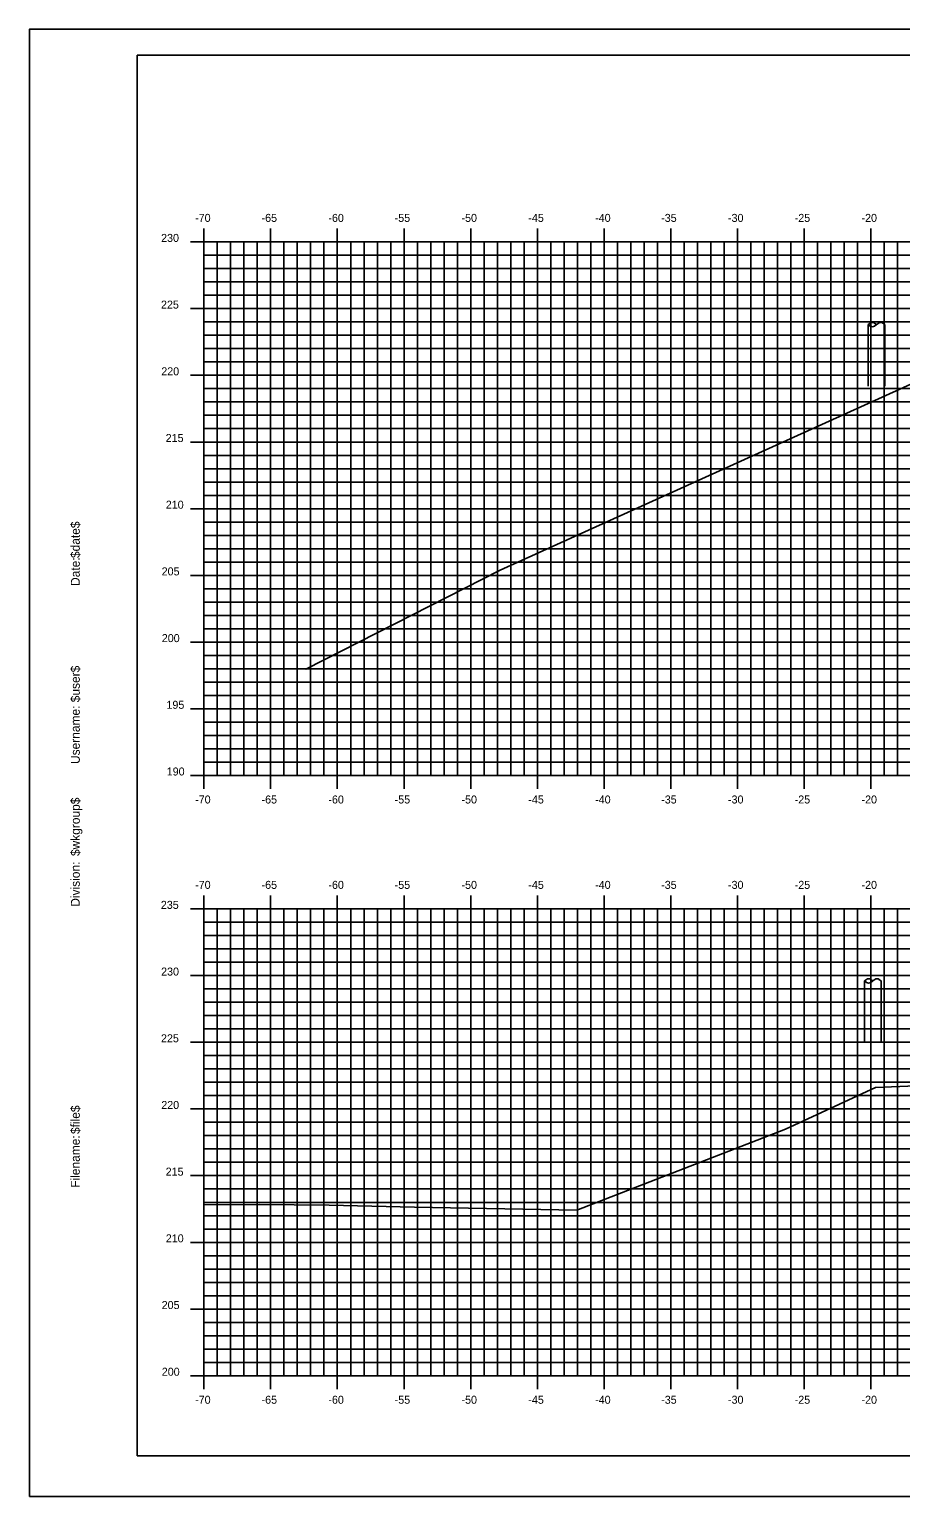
# Model space of a CAD drawing. Extents: x 1138098 to 1138268, y 608981 to 609091.
# Drawn here: x 1138097.8 to 1138163.2, y 608981.3 to 609091.3 of the extents above; entities that cross this region are included whole.
import ezdxf

# ---------------------------------------------------------------- set-up
doc = ezdxf.new("R2010")
doc.units = 0
for name, color, linetype in [('BORDER', 7, 'Continuous'), ('H_V ANNOTATION', 7, 'Continuous'), ('MAJOR', 7, 'Continuous'), ('MINOR', 7, 'Continuous'), ('PLOT BOUNDARY', 7, 'Continuous'), ('S_Roadway_Centerline', 7, 'Continuous'), ('S_Utilities_Pole_Power', 7, 'Continuous')]:
    doc.layers.add(name, color=color, linetype=linetype)

msp = doc.modelspace()

# ---------------------------------------------------------------- linework, layer by layer
at = {"layer": 'BORDER'}
msp.add_lwpolyline([(1138105.92, 608984.34), (1138265.92, 608984.34), (1138265.92, 609089.34), (1138105.92, 609089.34)], close=True, dxfattribs=at)
at = {"layer": 'MAJOR'}
for p, q in [((1138110.92, 609076.34), (1138110.92, 609075.34)), ((1138115.92, 609076.34), (1138115.92, 609075.34)), ((1138120.92, 609076.34), (1138120.92, 609075.34)), ((1138125.92, 609076.34), (1138125.92, 609075.34)), ((1138130.92, 609076.34), (1138130.92, 609075.34)), ((1138135.92, 609076.34), (1138135.92, 609075.34)), ((1138140.92, 609076.34), (1138140.92, 609075.34)), ((1138145.92, 609076.34), (1138145.92, 609075.34)), ((1138150.92, 609076.34), (1138150.92, 609075.34)), ((1138155.92, 609076.34), (1138155.92, 609075.34)), ((1138160.92, 609076.34), (1138160.92, 609075.34)), ((1138109.92, 609075.34), (1138110.92, 609075.34)), ((1138110.92, 609075.34), (1138250.92, 609075.34)), ((1138110.92, 609035.34), (1138110.92, 609075.34)), ((1138110.92, 609035.34), (1138110.92, 609075.34)), ((1138110.92, 609075.34), (1138250.92, 609075.34)), ((1138115.92, 609035.34), (1138115.92, 609075.34)), ((1138120.92, 609035.34), (1138120.92, 609075.34)), ((1138125.92, 609035.34), (1138125.92, 609075.34)), ((1138130.92, 609035.34), (1138130.92, 609075.34)), ((1138135.92, 609035.34), (1138135.92, 609075.34)), ((1138140.92, 609035.34), (1138140.92, 609075.34)), ((1138145.92, 609035.34), (1138145.92, 609075.34)), ((1138150.92, 609035.34), (1138150.92, 609075.34)), ((1138155.92, 609035.34), (1138155.92, 609075.34)), ((1138160.92, 609035.34), (1138160.92, 609075.34)), ((1138109.92, 609070.34), (1138110.92, 609070.34)), ((1138110.92, 609070.34), (1138250.92, 609070.34)), ((1138109.92, 609065.34), (1138110.92, 609065.34)), ((1138110.92, 609065.34), (1138250.92, 609065.34)), ((1138109.92, 609060.34), (1138110.92, 609060.34)), ((1138110.92, 609060.34), (1138250.92, 609060.34)), ((1138109.92, 609055.34), (1138110.92, 609055.34)), ((1138110.92, 609055.34), (1138250.92, 609055.34)), ((1138109.92, 609050.34), (1138110.92, 609050.34)), ((1138110.92, 609050.34), (1138250.92, 609050.34)), ((1138109.92, 609045.34), (1138110.92, 609045.34)), ((1138110.92, 609045.34), (1138250.92, 609045.34)), ((1138109.92, 609040.34), (1138110.92, 609040.34)), ((1138110.92, 609040.34), (1138250.92, 609040.34)), ((1138109.92, 609035.34), (1138110.92, 609035.34)), ((1138110.92, 609035.34), (1138250.92, 609035.34)), ((1138110.92, 609035.34), (1138250.92, 609035.34)), ((1138110.92, 609034.33), (1138110.92, 609035.34)), ((1138115.92, 609034.33), (1138115.92, 609035.34)), ((1138120.92, 609034.33), (1138120.92, 609035.34)), ((1138125.92, 609034.33), (1138125.92, 609035.34)), ((1138130.92, 609034.33), (1138130.92, 609035.34)), ((1138135.92, 609034.33), (1138135.92, 609035.34)), ((1138140.92, 609034.33), (1138140.92, 609035.34)), ((1138145.92, 609034.33), (1138145.92, 609035.34)), ((1138150.92, 609034.33), (1138150.92, 609035.34)), ((1138155.92, 609034.33), (1138155.92, 609035.34)), ((1138160.92, 609034.33), (1138160.92, 609035.34)), ((1138110.92, 609026.34), (1138110.92, 609025.34)), ((1138115.92, 609026.34), (1138115.92, 609025.34)), ((1138120.92, 609026.34), (1138120.92, 609025.34)), ((1138125.92, 609026.34), (1138125.92, 609025.34)), ((1138130.92, 609026.34), (1138130.92, 609025.34)), ((1138135.92, 609026.34), (1138135.92, 609025.34)), ((1138140.92, 609026.34), (1138140.92, 609025.34)), ((1138145.92, 609026.34), (1138145.92, 609025.34)), ((1138150.92, 609026.34), (1138150.92, 609025.34)), ((1138155.92, 609026.34), (1138155.92, 609025.34)), ((1138160.92, 609026.34), (1138160.92, 609025.34)), ((1138109.92, 609025.34), (1138110.92, 609025.34)), ((1138110.92, 609025.34), (1138250.92, 609025.34)), ((1138110.92, 608990.34), (1138110.92, 609025.34)), ((1138110.92, 608990.34), (1138110.92, 609025.34)), ((1138110.92, 609025.34), (1138250.92, 609025.34)), ((1138115.92, 608990.34), (1138115.92, 609025.34)), ((1138120.92, 608990.34), (1138120.92, 609025.34)), ((1138125.92, 608990.34), (1138125.92, 609025.34)), ((1138130.92, 608990.34), (1138130.92, 609025.34)), ((1138135.92, 608990.34), (1138135.92, 609025.34)), ((1138140.92, 608990.34), (1138140.92, 609025.34)), ((1138145.92, 608990.34), (1138145.92, 609025.34)), ((1138150.92, 608990.34), (1138150.92, 609025.34)), ((1138155.92, 608990.34), (1138155.92, 609025.34)), ((1138160.92, 608990.34), (1138160.92, 609025.34)), ((1138109.92, 609020.34), (1138110.92, 609020.34)), ((1138110.92, 609020.34), (1138250.92, 609020.34)), ((1138109.92, 609015.34), (1138110.92, 609015.34)), ((1138110.92, 609015.34), (1138250.92, 609015.34)), ((1138109.92, 609010.34), (1138110.92, 609010.34)), ((1138110.92, 609010.34), (1138250.92, 609010.34)), ((1138109.92, 609005.34), (1138110.92, 609005.34)), ((1138110.92, 609005.34), (1138250.92, 609005.34)), ((1138109.92, 609000.34), (1138110.92, 609000.34)), ((1138110.92, 609000.34), (1138250.92, 609000.34)), ((1138109.92, 608995.34), (1138110.92, 608995.34)), ((1138110.92, 608995.34), (1138250.92, 608995.34)), ((1138109.92, 608990.34), (1138110.92, 608990.34)), ((1138110.92, 608990.34), (1138250.92, 608990.34)), ((1138110.92, 608990.34), (1138250.92, 608990.34)), ((1138110.92, 608989.33), (1138110.92, 608990.34)), ((1138115.92, 608989.33), (1138115.92, 608990.34)), ((1138120.92, 608989.33), (1138120.92, 608990.34)), ((1138125.92, 608989.33), (1138125.92, 608990.34)), ((1138130.92, 608989.33), (1138130.92, 608990.34)), ((1138135.92, 608989.33), (1138135.92, 608990.34)), ((1138140.92, 608989.33), (1138140.92, 608990.34)), ((1138145.92, 608989.33), (1138145.92, 608990.34)), ((1138150.92, 608989.33), (1138150.92, 608990.34)), ((1138155.92, 608989.33), (1138155.92, 608990.34)), ((1138160.92, 608989.33), (1138160.92, 608990.34))]:
    msp.add_line(p, q, dxfattribs=at)
at = {"layer": 'MINOR'}
for p, q in [((1138111.92, 609035.34), (1138111.92, 609075.34)), ((1138112.92, 609035.34), (1138112.92, 609075.34)), ((1138113.92, 609035.34), (1138113.92, 609075.34)), ((1138114.92, 609035.34), (1138114.92, 609075.34)), ((1138116.92, 609035.34), (1138116.92, 609075.34)), ((1138117.92, 609035.34), (1138117.92, 609075.34)), ((1138118.92, 609035.34), (1138118.92, 609075.34)), ((1138119.92, 609035.34), (1138119.92, 609075.34)), ((1138121.92, 609035.34), (1138121.92, 609075.34)), ((1138122.92, 609035.34), (1138122.92, 609075.34)), ((1138123.92, 609035.34), (1138123.92, 609075.34)), ((1138124.92, 609035.34), (1138124.92, 609075.34)), ((1138126.92, 609035.34), (1138126.92, 609075.34)), ((1138127.92, 609035.34), (1138127.92, 609075.34)), ((1138128.92, 609035.34), (1138128.92, 609075.34)), ((1138129.92, 609035.34), (1138129.92, 609075.34)), ((1138131.92, 609035.34), (1138131.92, 609075.34)), ((1138132.92, 609035.34), (1138132.92, 609075.34)), ((1138133.92, 609035.34), (1138133.92, 609075.34)), ((1138134.92, 609035.34), (1138134.92, 609075.34)), ((1138136.92, 609035.34), (1138136.92, 609075.34)), ((1138137.92, 609035.34), (1138137.92, 609075.34)), ((1138138.92, 609035.34), (1138138.92, 609075.34)), ((1138139.92, 609035.34), (1138139.92, 609075.34)), ((1138141.92, 609035.34), (1138141.92, 609075.34)), ((1138142.92, 609035.34), (1138142.92, 609075.34)), ((1138143.92, 609035.34), (1138143.92, 609075.34)), ((1138144.92, 609035.34), (1138144.92, 609075.34)), ((1138146.92, 609035.34), (1138146.92, 609075.34)), ((1138147.92, 609035.34), (1138147.92, 609075.34)), ((1138148.92, 609035.34), (1138148.92, 609075.34)), ((1138149.92, 609035.34), (1138149.92, 609075.34)), ((1138151.92, 609035.34), (1138151.92, 609075.34)), ((1138152.92, 609035.34), (1138152.92, 609075.34)), ((1138153.92, 609035.34), (1138153.92, 609075.34)), ((1138154.92, 609035.34), (1138154.92, 609075.34)), ((1138156.92, 609035.34), (1138156.92, 609075.34)), ((1138157.92, 609035.34), (1138157.92, 609075.34)), ((1138158.92, 609035.34), (1138158.92, 609075.34)), ((1138159.92, 609035.34), (1138159.92, 609075.34)), ((1138161.92, 609035.34), (1138161.92, 609075.34)), ((1138162.92, 609035.34), (1138162.92, 609075.34)), ((1138110.92, 609074.34), (1138250.92, 609074.34)), ((1138110.92, 609074.34), (1138111.92, 609074.34)), ((1138110.92, 609073.34), (1138250.92, 609073.34)), ((1138110.92, 609073.34), (1138111.92, 609073.34)), ((1138110.92, 609072.34), (1138250.92, 609072.34)), ((1138110.92, 609072.34), (1138111.92, 609072.34)), ((1138110.92, 609071.34), (1138250.92, 609071.34)), ((1138110.92, 609071.34), (1138111.92, 609071.34)), ((1138110.92, 609069.34), (1138250.92, 609069.34)), ((1138110.92, 609069.34), (1138111.92, 609069.34)), ((1138110.92, 609068.34), (1138250.92, 609068.34)), ((1138110.92, 609068.34), (1138111.92, 609068.34)), ((1138110.92, 609067.34), (1138250.92, 609067.34)), ((1138110.92, 609067.34), (1138111.92, 609067.34)), ((1138110.92, 609066.34), (1138250.92, 609066.34)), ((1138110.92, 609066.34), (1138111.92, 609066.34)), ((1138110.92, 609064.34), (1138250.92, 609064.34)), ((1138110.92, 609064.34), (1138111.92, 609064.34)), ((1138110.92, 609063.34), (1138250.92, 609063.34)), ((1138110.92, 609063.34), (1138111.92, 609063.34)), ((1138110.92, 609062.34), (1138250.92, 609062.34)), ((1138110.92, 609062.34), (1138111.92, 609062.34)), ((1138110.92, 609061.34), (1138250.92, 609061.34)), ((1138110.92, 609061.34), (1138111.92, 609061.34)), ((1138110.92, 609059.34), (1138250.92, 609059.34)), ((1138110.92, 609059.34), (1138111.92, 609059.34)), ((1138110.92, 609058.34), (1138250.92, 609058.34)), ((1138110.92, 609058.34), (1138111.92, 609058.34)), ((1138110.92, 609057.34), (1138250.92, 609057.34)), ((1138110.92, 609057.34), (1138111.92, 609057.34)), ((1138110.92, 609056.34), (1138250.92, 609056.34)), ((1138110.92, 609056.34), (1138111.92, 609056.34)), ((1138110.92, 609054.34), (1138250.92, 609054.34)), ((1138110.92, 609054.34), (1138111.92, 609054.34)), ((1138110.92, 609053.34), (1138250.92, 609053.34)), ((1138110.92, 609053.34), (1138111.92, 609053.34)), ((1138110.92, 609052.34), (1138250.92, 609052.34)), ((1138110.92, 609052.34), (1138111.92, 609052.34)), ((1138110.92, 609051.34), (1138250.92, 609051.34)), ((1138110.92, 609051.34), (1138111.92, 609051.34)), ((1138110.92, 609049.34), (1138250.92, 609049.34)), ((1138110.92, 609049.34), (1138111.92, 609049.34)), ((1138110.92, 609048.34), (1138250.92, 609048.34)), ((1138110.92, 609048.34), (1138111.92, 609048.34)), ((1138110.92, 609047.34), (1138250.92, 609047.34)), ((1138110.92, 609047.34), (1138111.92, 609047.34)), ((1138110.92, 609046.34), (1138250.92, 609046.34)), ((1138110.92, 609046.34), (1138111.92, 609046.34)), ((1138110.92, 609044.34), (1138250.92, 609044.34)), ((1138110.92, 609044.34), (1138111.92, 609044.34)), ((1138110.92, 609043.34), (1138250.92, 609043.34)), ((1138110.92, 609043.34), (1138111.92, 609043.34)), ((1138110.92, 609042.34), (1138250.92, 609042.34)), ((1138110.92, 609042.34), (1138111.92, 609042.34)), ((1138110.92, 609041.34), (1138250.92, 609041.34)), ((1138110.92, 609041.34), (1138111.92, 609041.34)), ((1138110.92, 609039.34), (1138250.92, 609039.34)), ((1138110.92, 609039.34), (1138111.92, 609039.34)), ((1138110.92, 609038.34), (1138250.92, 609038.34)), ((1138110.92, 609038.34), (1138111.92, 609038.34)), ((1138110.92, 609037.34), (1138250.92, 609037.34)), ((1138110.92, 609037.34), (1138111.92, 609037.34)), ((1138110.92, 609036.34), (1138250.92, 609036.34)), ((1138110.92, 609036.34), (1138111.92, 609036.34)), ((1138111.92, 608990.34), (1138111.92, 609025.34)), ((1138112.92, 608990.34), (1138112.92, 609025.34)), ((1138113.92, 608990.34), (1138113.92, 609025.34)), ((1138114.92, 608990.34), (1138114.92, 609025.34)), ((1138116.92, 608990.34), (1138116.92, 609025.34)), ((1138117.92, 608990.34), (1138117.92, 609025.34)), ((1138118.92, 608990.34), (1138118.92, 609025.34)), ((1138119.92, 608990.34), (1138119.92, 609025.34)), ((1138121.92, 608990.34), (1138121.92, 609025.34)), ((1138122.92, 608990.34), (1138122.92, 609025.34)), ((1138123.92, 608990.34), (1138123.92, 609025.34)), ((1138124.92, 608990.34), (1138124.92, 609025.34)), ((1138126.92, 608990.34), (1138126.92, 609025.34)), ((1138127.92, 608990.34), (1138127.92, 609025.34)), ((1138128.92, 608990.34), (1138128.92, 609025.34)), ((1138129.92, 608990.34), (1138129.92, 609025.34)), ((1138131.92, 608990.34), (1138131.92, 609025.34)), ((1138132.92, 608990.34), (1138132.92, 609025.34)), ((1138133.92, 608990.34), (1138133.92, 609025.34)), ((1138134.92, 608990.34), (1138134.92, 609025.34)), ((1138136.92, 608990.34), (1138136.92, 609025.34)), ((1138137.92, 608990.34), (1138137.92, 609025.34)), ((1138138.92, 608990.34), (1138138.92, 609025.34)), ((1138139.92, 608990.34), (1138139.92, 609025.34)), ((1138141.92, 608990.34), (1138141.92, 609025.34)), ((1138142.92, 608990.34), (1138142.92, 609025.34)), ((1138143.92, 608990.34), (1138143.92, 609025.34)), ((1138144.92, 608990.34), (1138144.92, 609025.34)), ((1138146.92, 608990.34), (1138146.92, 609025.34)), ((1138147.92, 608990.34), (1138147.92, 609025.34)), ((1138148.92, 608990.34), (1138148.92, 609025.34)), ((1138149.92, 608990.34), (1138149.92, 609025.34)), ((1138151.92, 608990.34), (1138151.92, 609025.34)), ((1138152.92, 608990.34), (1138152.92, 609025.34)), ((1138153.92, 608990.34), (1138153.92, 609025.34)), ((1138154.92, 608990.34), (1138154.92, 609025.34)), ((1138156.92, 608990.34), (1138156.92, 609025.34)), ((1138157.92, 608990.34), (1138157.92, 609025.34)), ((1138158.92, 608990.34), (1138158.92, 609025.34)), ((1138159.92, 608990.34), (1138159.92, 609025.34)), ((1138161.92, 608990.34), (1138161.92, 609025.34)), ((1138162.92, 608990.34), (1138162.92, 609025.34)), ((1138110.92, 609024.34), (1138250.92, 609024.34)), ((1138110.92, 609024.34), (1138111.92, 609024.34)), ((1138110.92, 609023.34), (1138250.92, 609023.34)), ((1138110.92, 609023.34), (1138111.92, 609023.34)), ((1138110.92, 609022.34), (1138250.92, 609022.34)), ((1138110.92, 609022.34), (1138111.92, 609022.34)), ((1138110.92, 609021.34), (1138250.92, 609021.34)), ((1138110.92, 609021.34), (1138111.92, 609021.34)), ((1138110.92, 609019.34), (1138250.92, 609019.34)), ((1138110.92, 609019.34), (1138111.92, 609019.34)), ((1138110.92, 609018.34), (1138250.92, 609018.34)), ((1138110.92, 609018.34), (1138111.92, 609018.34)), ((1138110.92, 609017.34), (1138250.92, 609017.34)), ((1138110.92, 609017.34), (1138111.92, 609017.34)), ((1138110.92, 609016.34), (1138250.92, 609016.34)), ((1138110.92, 609016.34), (1138111.92, 609016.34)), ((1138110.92, 609014.34), (1138250.92, 609014.34)), ((1138110.92, 609014.34), (1138111.92, 609014.34)), ((1138110.92, 609013.34), (1138250.92, 609013.34)), ((1138110.92, 609013.34), (1138111.92, 609013.34)), ((1138110.92, 609012.34), (1138250.92, 609012.34)), ((1138110.92, 609012.34), (1138111.92, 609012.34)), ((1138110.92, 609011.34), (1138250.92, 609011.34)), ((1138110.92, 609011.34), (1138111.92, 609011.34)), ((1138110.92, 609009.34), (1138250.92, 609009.34)), ((1138110.92, 609009.34), (1138111.92, 609009.34)), ((1138110.92, 609008.34), (1138250.92, 609008.34)), ((1138110.92, 609008.34), (1138111.92, 609008.34)), ((1138110.92, 609007.34), (1138250.92, 609007.34)), ((1138110.92, 609007.34), (1138111.92, 609007.34)), ((1138110.92, 609006.34), (1138250.92, 609006.34)), ((1138110.92, 609006.34), (1138111.92, 609006.34)), ((1138110.92, 609004.34), (1138250.92, 609004.34)), ((1138110.92, 609004.34), (1138111.92, 609004.34)), ((1138110.92, 609003.34), (1138250.92, 609003.34)), ((1138110.92, 609003.34), (1138111.92, 609003.34)), ((1138110.92, 609002.34), (1138250.92, 609002.34)), ((1138110.92, 609002.34), (1138111.92, 609002.34)), ((1138110.92, 609001.34), (1138250.92, 609001.34)), ((1138110.92, 609001.34), (1138111.92, 609001.34)), ((1138110.92, 608999.34), (1138250.92, 608999.34)), ((1138110.92, 608999.34), (1138111.92, 608999.34)), ((1138110.92, 608998.34), (1138250.92, 608998.34)), ((1138110.92, 608998.34), (1138111.92, 608998.34)), ((1138110.92, 608997.34), (1138250.92, 608997.34)), ((1138110.92, 608997.34), (1138111.92, 608997.34)), ((1138110.92, 608996.34), (1138250.92, 608996.34)), ((1138110.92, 608996.34), (1138111.92, 608996.34)), ((1138110.92, 608994.34), (1138250.92, 608994.34)), ((1138110.92, 608994.34), (1138111.92, 608994.34)), ((1138110.92, 608993.34), (1138250.92, 608993.34)), ((1138110.92, 608993.34), (1138111.92, 608993.34)), ((1138110.92, 608992.34), (1138250.92, 608992.34)), ((1138110.92, 608992.34), (1138111.92, 608992.34)), ((1138110.92, 608991.34), (1138250.92, 608991.34)), ((1138110.92, 608991.34), (1138111.92, 608991.34))]:
    msp.add_line(p, q, dxfattribs=at)
at = {"layer": 'PLOT BOUNDARY'}
msp.add_lwpolyline([(1138097.83, 608981.28), (1138267.83, 608981.28), (1138267.83, 609091.28), (1138097.83, 609091.28)], close=True, dxfattribs=at)
at = {"layer": 'S_Roadway_Centerline'}
for points in [[(1138110.92, 609043.36), (1138118.56, 609043.32), (1138133.12, 609050.73), (1138168.66, 609066.82), (1138168.66, 609066.82), (1138168.66, 609066.82), (1138168.86, 609066.84), (1138171.43, 609066.88), (1138180.68, 609065.74), (1138192.58, 609065.28), (1138193.76, 609065.25), (1138195.72, 609065.03), (1138197.91, 609064.27), (1138240.27, 609043.85), (1138240.39, 609043.84), (1138242.92, 609043.82), (1138250.92, 609043.73)], [(1138110.92, 609003.16), (1138115.05, 609003.19), (1138120.3, 609003.14), (1138126.71, 609002.99), (1138138.88, 609002.75), (1138154.53, 609008.82), (1138161.27, 609011.94), (1138164.3, 609012.07), (1138165.14, 609011.78), (1138168.12, 609016.15), (1138168.67, 609016.28), (1138177.96, 609016.4), (1138180.85, 609016.49), (1138184.16, 609016.36), (1138186.04, 609016.35), (1138192.39, 609016.2), (1138193.87, 609015.73), (1138196.51, 609013.46), (1138198.08, 609013.45), (1138223.62, 609001.75), (1138226.89, 609000.29), (1138227.92, 609000.31), (1138250.92, 609000.39)]]:
    msp.add_lwpolyline(points, dxfattribs=at)
at = {"layer": 'S_Utilities_Pole_Power'}
for p, q in [((1138160.72, 609069.14), (1138160.88, 609069.25)), ((1138160.72, 609064.52), (1138160.73, 609069.14)), ((1138160.88, 609069.03), (1138160.72, 609069.14)), ((1138161.19, 609069.25), (1138161.35, 609069.14)), ((1138161.35, 609069.14), (1138161.19, 609069.03)), ((1138161.51, 609069.25), (1138161.35, 609069.14)), ((1138161.97, 609069.14), (1138161.82, 609069.25)), ((1138161.97, 609064.52), (1138161.98, 609069.14)), ((1138160.44, 609019.94), (1138160.59, 609020.05)), ((1138160.44, 609015.32), (1138160.44, 609019.94)), ((1138160.59, 609019.83), (1138160.44, 609019.94)), ((1138160.91, 609020.05), (1138161.06, 609019.94)), ((1138161.06, 609019.94), (1138160.91, 609019.83)), ((1138161.22, 609020.05), (1138161.06, 609019.94)), ((1138161.69, 609019.94), (1138161.53, 609020.05)), ((1138161.69, 609015.32), (1138161.69, 609019.94))]:
    msp.add_line(p, q, dxfattribs=at)
for centre, start, end in [((1138161.04, 609069.03), 90, 125.2644), ((1138161.04, 609069.25), 234.7356, 270), ((1138161.04, 609069.03), 54.7356, 90), ((1138161.04, 609069.25), 270, 305.2644), ((1138161.66, 609069.03), 90, 125.2644), ((1138161.66, 609069.03), 54.7356, 90), ((1138160.75, 609019.83), 90, 125.2644), ((1138160.75, 609020.05), 234.7356, 270), ((1138160.75, 609019.83), 54.7356, 90), ((1138160.75, 609020.05), 270, 305.2644), ((1138161.38, 609019.83), 90, 125.2644), ((1138161.38, 609019.83), 54.7356, 90)]:
    msp.add_arc(centre, 0.271, start, end, dxfattribs=at)

# ---------------------------------------------------------------- texts
at = {"layer": 'BORDER'}
for s, p in [('$date$', (1138101.61, 609051.64)), ('Date:', (1138101.61, 609049.55)), ('$user$', (1138101.61, 609040.83)), ('Username:', (1138101.61, 609036.2)), ('$wkgroup$', (1138101.61, 609029.3)), ('Division:', (1138101.61, 609025.5)), ('$file$', (1138101.61, 609008.46)), ('Filename:', (1138101.61, 609004.43))]:
    msp.add_text(s, height=0.67, rotation=90, dxfattribs=at).set_placement(p)
at = {"layer": 'H_V ANNOTATION'}
for s, p in [('-70', (1138110.26, 609076.84)), ('-65', (1138115.24, 609076.84)), ('-60', (1138120.25, 609076.84)), ('-55', (1138125.22, 609076.84)), ('-50', (1138130.23, 609076.84)), ('-45', (1138135.24, 609076.84)), ('-40', (1138140.25, 609076.84)), ('-35', (1138145.2, 609076.84)), ('-30', (1138150.21, 609076.84)), ('-25', (1138155.21, 609076.84)), ('-20', (1138160.22, 609076.84)), ('230', (1138107.71, 609075.34)), ('225', (1138107.7, 609070.34)), ('220', (1138107.72, 609065.34)), ('215', (1138108.05, 609060.34)), ('210', (1138108.06, 609055.34)), ('205', (1138107.75, 609050.34)), ('200', (1138107.76, 609045.34)), ('195', (1138108.11, 609040.34)), ('190', (1138108.13, 609035.34)), ('-70', (1138110.26, 609033.24)), ('-65', (1138115.24, 609033.24)), ('-60', (1138120.25, 609033.24)), ('-55', (1138125.22, 609033.24)), ('-50', (1138130.23, 609033.24)), ('-45', (1138135.24, 609033.24)), ('-40', (1138140.25, 609033.24)), ('-35', (1138145.2, 609033.24)), ('-30', (1138150.21, 609033.24)), ('-25', (1138155.21, 609033.24)), ('-20', (1138160.22, 609033.24)), ('-70', (1138110.26, 609026.84)), ('-65', (1138115.24, 609026.84)), ('-60', (1138120.25, 609026.84)), ('-55', (1138125.22, 609026.84)), ('-50', (1138130.23, 609026.84)), ('-45', (1138135.24, 609026.84)), ('-40', (1138140.25, 609026.84)), ('-35', (1138145.2, 609026.84)), ('-30', (1138150.21, 609026.84)), ('-25', (1138155.21, 609026.84)), ('-20', (1138160.22, 609026.84)), ('235', (1138107.69, 609025.34)), ('230', (1138107.71, 609020.34)), ('225', (1138107.7, 609015.34)), ('220', (1138107.72, 609010.34)), ('215', (1138108.05, 609005.34)), ('210', (1138108.06, 609000.34)), ('205', (1138107.75, 608995.34)), ('200', (1138107.76, 608990.34)), ('-70', (1138110.26, 608988.24)), ('-65', (1138115.24, 608988.24)), ('-60', (1138120.25, 608988.24)), ('-55', (1138125.22, 608988.24)), ('-50', (1138130.23, 608988.24)), ('-45', (1138135.24, 608988.24)), ('-40', (1138140.25, 608988.24)), ('-35', (1138145.2, 608988.24)), ('-30', (1138150.21, 608988.24)), ('-25', (1138155.21, 608988.24)), ('-20', (1138160.22, 608988.24))]:
    msp.add_text(s, height=0.6, dxfattribs=at).set_placement(p)
at = {"layer": 'MAJOR'}
for p in [(1138110.92, 609035.34), (1138110.92, 608990.34)]:
    msp.add_text('-', height=0.006, dxfattribs=at).set_placement(p)

doc.saveas('drawing.dxf')
